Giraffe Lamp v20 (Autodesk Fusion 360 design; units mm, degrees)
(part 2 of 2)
sketch "Sketch2" plane through (0, 42, 0) normal (0, 1, 0) x axis (-1, 0, 0)
  line L1 (-90, 0) -> (-148, 0)
  line L2 (-90, 28) -> (-90, 0)
  line L3 (-148, 28) -> (-90, 28)
  line L4 (-148, 0) -> (-148, 28)
  line L5 (-125.9, 0) -> (-104.4, 0)
  line L6 (-125.9, 13) -> (-125.9, 0)
  line L7 (-104.4, 13) -> (-125.9, 13)
  line L8 (-104.4, 0) -> (-104.4, 13)
  line L9 (-93, 28) -> (-93, 3)
  line L10 (-148, 0) -> (-90, 0)
  line L11 (-148, 6.5) -> (-90, 6.5)
  line L12 (-148, 21.5) -> (-148, 6.5)
  line L13 (-90, 21.5) -> (-148, 21.5)
  line L14 (-90, 6.5) -> (-90, 21.5)
  line L15 (-103, 6.5) -> (-93, 6.5)
  line L16 (-103, 9.5) -> (-103, 6.5)
  line L17 (-93, 9.5) -> (-103, 9.5)
  line L18 (-93, 6.5) -> (-93, 9.5)
  line L19 (-145, 6.5) -> (-135, 6.5)
  line L20 (-145, 9.5) -> (-145, 6.5)
  line L21 (-135, 9.5) -> (-145, 9.5)
  line L22 (-135, 6.5) -> (-135, 9.5)
  line L23 (-103, 18.5) -> (-93, 18.5)
  line L24 (-103, 21.5) -> (-103, 18.5)
  line L25 (-93, 21.5) -> (-103, 21.5)
  line L26 (-93, 18.5) -> (-93, 21.5)
  line L27 (-145, 18.5) -> (-135, 18.5)
  line L28 (-145, 21.5) -> (-145, 18.5)
  line L29 (-135, 21.5) -> (-145, 21.5)
  line L30 (-135, 18.5) -> (-135, 21.5)
  point P6 (-104.4, 0)
  point P7 (-125.9, 0)
  point P9 (-104.4, 13)
  point P14 (-90, 6.5)
  point P17 (-90, 21.5)
  point P18 (-93, 6.5)
  point P19 (-103, 6.5)
  point P21 (-93, 9.5)
  dimension "d750" distance P6 P7 = 21.5
  dimension "d751" distance P6 P9 = 13 (= "10 mm + pcb_holder_thickness")
  dimension "d753" distance L8 L9 = 11.4
  dimension "d761" distance P14 P17 = 15 (= "Face1_to_2")
  dimension "d762" distance P18 P19 = 10
  dimension "d763" distance P18 P21 = 3 (= "pcb_holder_thickness")
  dimension "d766" R-Pattern1-uDistance = -42 (= "-pcb_X + 10 mm")
  dimension "d767" R-Pattern1-vDistance = 12 (= "Face1_to_2 - pcb_holder_thickness")
sketch "Sketch3" plane through (0, -13, 0) normal (0, -1, 0) x axis (1, 0, 0)
  line L1 (148, 0) -> (90, 0)
  line L2 (148, 28) -> (148, 0)
  line L3 (90, 28) -> (148, 28)
  line L4 (90, 0) -> (90, 28)
  line L5 (138, 28) -> (122, 28)
  line L6 (138, 25) -> (138, 28)
  line L7 (122, 25) -> (138, 25)
  line L8 (122, 28) -> (122, 25)
  line L9 (145, 28) -> (145, 3)
  point P6 (122, 28)
  point P7 (138, 28)
  point P9 (122, 25)
  dimension "d756" distance P6 P7 = 16
  dimension "d757" distance P6 P9 = 3
  dimension "d758" distance L6 L9 = 7
extrude "Extrude4" sketch "Sketch3" profile of L3 L5 L6 L7 L8 no distance stored
extrude "Extrude5" sketch "Sketch2" profile of L9 L11 L13 L15 L16 L17 L18 L19 L20 L21 L22 L23 L24 L25 L26 L27 L28 L29 L30 blind 10
fillet "Fillet1" radius 5
extrude "Extrude3" sketch "Sketch2" profile of L1 L5 L6 L7 L8 L10 no distance stored
position "Position8"
joint "Assemble25" alignAngle -30 alignOffsetX 0 alignOffsetY 0 alignOffsetZ 0
sketch "Sketch2" plane through (0, 3, 0) normal (0, 1, 0) x axis (-1, 0, 0)
  line L1 (264.3015, -79.5821) -> (253.0159, -61.0056)
  line L2 (261.7376, -81.1397) -> (264.3015, -79.5821)
  line L3 (250.2825, -62.2843) -> (261.7376, -81.1397)
  line L4 (346.5917, -63.6918) -> (423.9101, -61.7918)
  line L5 (346.518, -60.6927) -> (346.5917, -63.6918)
  line L6 (424.0216, -58.7881) -> (346.518, -60.6927)
  line L7 (404.6538, -49.3613) -> (406.365, -38.0363)
  line L8 (401.6874, -48.9131) -> (404.6538, -49.3613)
  line L9 (403.479, -37.0562) -> (401.6874, -48.9131)
  line L10 (381.5227, -41.8271) -> (391.5197, -41.5814)
  line L11 (381.7684, -51.8241) -> (381.5227, -41.8271)
  line L12 (378.7693, -51.8978) -> (381.7684, -51.8241)
  line L13 (378.5236, -41.9008) -> (378.7693, -51.8978)
  line L14 (363.5282, -42.2693) -> (378.5236, -41.9008)
  line L15 (363.7738, -52.2663) -> (363.5282, -42.2693)
  line L16 (360.7747, -52.34) -> (363.7738, -52.2663)
  line L17 (360.5291, -42.3447) -> (360.7747, -52.34)
  line L18 (352.5161, -42.5416) -> (360.5291, -42.3447)
  line L19 (338.4853, -45.7388) -> (331.2966, -32.4478)
  line L20 (335.8466, -47.166) -> (338.4853, -45.7388)
  line L21 (328.7104, -33.9723) -> (335.8466, -47.166)
  line L22 (303.2357, -50.7747) -> (328.7104, -33.9723)
  line L23 (301.5839, -48.2704) -> (303.2357, -50.7747)
  line L24 (327.5614, -31.1364) -> (301.5839, -48.2704)
  line L25 (253.0159, -61.0056) -> (293.885, -40.3968)
  line L26 (276.3126, -105.1308) -> (279.5515, -110.7585)
  line L27 (326.6272, -76.2737) -> (276.3126, -105.1308)
  line L28 (335.512, -91.6693) -> (326.6272, -76.2737)
  circle C1 centre (251.8048, -98.0857) radius 3
  circle C2 centre (297.583, -75.9965) radius 6
  arc A1 centre (237.9246, -55.6761) radius 14.0138 clockwise from (250.2825, -62.2843) to (248.2866, -65.1109)
  arc A2 centre (265.0043, -90.0088) radius 29.9898 clockwise from (265, -119.9986) to (248.2866, -65.1109)
  arc A3 centre (265.0004, -104.4994) radius 15.4992 clockwise from (278.1678, -112.6753) to (265, -119.9986)
  arc A4 centre (292.6106, -121.6427) radius 17.0002 clockwise from (278.1678, -112.6753) to (297.6595, -105.4096)
  arc A5 centre (305.9733, -78.6726) radius 27.9997 clockwise from (324.1949, -99.932) to (297.6595, -105.4096)
  arc A6 centre (382.7624, -168.2688) radius 90.0004 clockwise from (324.1949, -99.932) to (396.2531, -79.2852)
  arc A7 centre (399.9843, -54.5747) radius 24.9906 clockwise from (423.9101, -61.7918) to (396.2531, -79.2852)
  arc A8 centre (403.7415, -61.7856) radius 20.5005 clockwise from (411.4762, -42.8002) to (424.0216, -58.7881)
  arc A9 centre (401.093, -48.8166) radius 12.0003 clockwise from (406.365, -38.0363) to (411.4762, -42.8002)
  arc A10 centre (401.0931, -48.8167) radius 12 clockwise from (391.5197, -41.5814) to (403.479, -37.0562)
  arc A11 centre (352.0728, -24.5455) radius 18.0016 clockwise from (352.5161, -42.5416) to (340.0285, -37.9243)
  arc A12 centre (319.9606, -60.2216) radius 29.9982 clockwise from (331.2966, -32.4478) to (340.0285, -37.9243)
  arc A13 centre (320.0013, -60.1969) radius 30.0278 clockwise from (301.4762, -36.5645) to (327.5614, -31.1364)
  arc A14 centre (288.0365, -19.3769) radius 21.8183 clockwise from (301.4762, -36.5645) to (293.885, -40.3968)
extrude "Extrude2" cut sketch "Sketch2" profile of A4 A5 A6 L26 L27 L28 along a picked direction to an object
sketch "Sketch1" plane through (0, 0, 0) normal (0, -1, 0) x axis (1, 0, 0)
  line L1 (-253.0159, -61.0056) -> (-264.3015, -79.5821)
  line L2 (-293.8849, -40.3968) -> (-253.0159, -61.0056)
  line L3 (-301.5839, -48.2704) -> (-327.5614, -31.1364)
  line L4 (-303.2357, -50.7747) -> (-301.5839, -48.2704)
  line L5 (-328.7104, -33.9723) -> (-303.2357, -50.7747)
  line L6 (-335.8466, -47.166) -> (-328.7104, -33.9723)
  line L7 (-338.4853, -45.7388) -> (-335.8466, -47.166)
  line L8 (-331.2966, -32.4478) -> (-338.4853, -45.7388)
  line L9 (-360.5291, -42.3447) -> (-352.516, -42.5416)
  line L10 (-360.7747, -52.34) -> (-360.5291, -42.3447)
  line L11 (-363.7738, -52.2663) -> (-360.7747, -52.34)
  line L12 (-363.5282, -42.2693) -> (-363.7738, -52.2663)
  line L13 (-378.5236, -41.9008) -> (-363.5282, -42.2693)
  line L14 (-378.7693, -51.8978) -> (-378.5236, -41.9008)
  line L15 (-381.7684, -51.8241) -> (-378.7693, -51.8978)
  line L16 (-381.5227, -41.8271) -> (-381.7684, -51.8241)
  line L17 (-391.5196, -41.5814) -> (-381.5227, -41.8271)
  line L18 (-401.6874, -48.9131) -> (-403.479, -37.0562)
  line L19 (-404.6538, -49.3613) -> (-401.6874, -48.9131)
  line L20 (-406.3649, -38.0363) -> (-404.6538, -49.3613)
  line L21 (-346.518, -60.6927) -> (-424.0216, -58.7882)
  line L22 (-346.5917, -63.6918) -> (-346.518, -60.6927)
  line L23 (-423.91, -61.7918) -> (-346.5917, -63.6918)
  line L24 (-261.7375, -81.1397) -> (-250.2825, -62.2843)
  line L25 (-264.3015, -79.5821) -> (-261.7375, -81.1397)
  line L26 (-326.6271, -76.2737) -> (-335.512, -91.6693)
  line L27 (-276.3126, -105.1309) -> (-326.6271, -76.2737)
  line L28 (-279.5515, -110.7585) -> (-276.3126, -105.1309)
  circle C1 centre (-251.8048, -98.0857) radius 3
  circle C2 centre (-297.583, -75.9965) radius 6
  arc A1 centre (-288.0365, -19.3769) radius 21.8183 clockwise from (-293.8849, -40.3968) to (-301.4762, -36.5645)
  arc A2 centre (-320.0013, -60.1969) radius 30.0278 clockwise from (-327.5614, -31.1364) to (-301.4762, -36.5645)
  arc A3 centre (-319.9606, -60.2216) radius 29.9982 clockwise from (-340.0285, -37.9243) to (-331.2966, -32.4478)
  arc A4 centre (-352.0727, -24.5455) radius 18.0016 clockwise from (-340.0285, -37.9243) to (-352.516, -42.5416)
  arc A5 centre (-401.0931, -48.8167) radius 12 clockwise from (-403.479, -37.0562) to (-391.5196, -41.5814)
  arc A6 centre (-401.093, -48.8166) radius 12.0003 clockwise from (-411.4762, -42.8002) to (-406.3649, -38.0363)
  arc A7 centre (-403.7415, -61.7856) radius 20.5005 clockwise from (-424.0216, -58.7882) to (-411.4762, -42.8002)
  arc A8 centre (-399.9843, -54.5747) radius 24.9906 clockwise from (-396.2531, -79.2852) to (-423.91, -61.7918)
  arc A9 centre (-382.7624, -168.2688) radius 90.0004 clockwise from (-396.2531, -79.2852) to (-335.512, -91.6693)
  arc A10 centre (-292.6105, -121.6427) radius 17.0002 clockwise from (-279.5515, -110.7585) to (-278.1678, -112.6753)
  arc A11 centre (-265.0004, -104.4994) radius 15.4992 clockwise from (-265, -119.9986) to (-278.1678, -112.6753)
  arc A12 centre (-265.0042, -90.0088) radius 29.9898 clockwise from (-248.2865, -65.1109) to (-265, -119.9986)
  arc A13 centre (-237.9246, -55.6761) radius 14.0138 clockwise from (-248.2865, -65.1109) to (-250.2825, -62.2843)
extrude "Extrude1" new body sketch "Thug Life glasses" profile of L1 L2 L3 L4 L5 L6 L7 L8 L9 L10 L11 L19 L12 L13 L14 L15 L16 L17 along normal blind 3 (= "Thickness")
sketch "Sketch4" plane through (0, 3, 0) normal (0, 1, 0) x axis (-1, 0, 0)
  line L1 (179.3475, -84.0435) -> (190, -82.8095)
  line L2 (177.7875, -81.2041) -> (178.0387, -83.3727)
  line L3 (177.209, -81.2711) -> (177.7875, -81.2041)
  curve K1 (177.209, -81.2711) -> (157.551, -61.7546)
  line L4 (156.5, -61.7546) -> (157.551, -61.7546)
  curve K2 (156.5, -61.7546) -> (144.8507, -76.5991)
  line L5 (138, -96.1735) -> (144.8507, -76.5991)
  line L6 (138, -120) -> (138, -96.1735)
  line L7 (190, -101.0735) -> (138, -120)
  line L8 (190, -99.1735) -> (190, -101.0735)
  line L9 (159.5, -99.1735) -> (190, -99.1735)
  line L10 (159.5, -96.1735) -> (159.5, -99.1735)
  line L11 (190, -96.1735) -> (159.5, -96.1735)
  line L12 (190, -82.8095) -> (190, -96.1735)
  arc A1 centre (193.315, -55.1792) radius 32.0662 clockwise from (179.3475, -84.0435) to (178.0387, -83.3727)
sketch "Sketch3" plane through (0, 3, 0) normal (0, 1, 0) x axis (-1, 0, 0)
  line L1 (394, -22.5177) -> (371, -22.5177)
  line L2 (414.3235, 142.703) -> (429.2349, 121.5322)
  line L3 (394, 142.703) -> (414.3235, 142.703)
  line L4 (394, 55.5559) -> (394, 142.703)
  line L5 (391, 55.5559) -> (394, 55.5559)
  line L6 (391, 142.703) -> (391, 55.5559)
  line L7 (376, 142.703) -> (391, 142.703)
  line L8 (376, 55.5559) -> (376, 142.703)
  line L9 (373, 55.5559) -> (376, 55.5559)
  line L10 (373, 142.703) -> (373, 55.5559)
  line L11 (352.6765, 142.703) -> (373, 142.703)
  line L12 (336.5, 122.4823) -> (352.6765, 142.703)
  circle C1 centre (356.5, 120.1478) radius 6
  circle C2 centre (411.5, 120.1478) radius 6
  arc A1 centre (306.9189, 35.4376) radius 50 clockwise from (340.5, 72.4823) to (352.9482, 15.9105)
  arc A2 centre (382.5, 3.3737) radius 32.1011 clockwise from (350.9441, -2.5177) to (352.9482, 15.9105)
  arc A3 centre (375.5195, 2.0704) radius 25 clockwise from (371, -22.5177) to (350.9441, -2.5177)
  arc A4 centre (389.4805, 2.0704) radius 25 clockwise from (414.0559, -2.5177) to (394, -22.5177)
  arc A5 centre (382.5, 3.3737) radius 32.1011 clockwise from (412.0518, 15.9105) to (414.0559, -2.5177)
  arc A6 centre (458.0811, 35.4376) radius 50 clockwise from (412.0518, 15.9105) to (424.5, 72.4823)
  arc A7 centre (399.9091, 99.6096) radius 36.6142 clockwise from (429.2349, 121.5322) to (424.5, 72.4823)
  arc A8 centre (365.0909, 99.6096) radius 36.6142 clockwise from (340.5, 72.4823) to (336.5, 122.4823)
copy_paste "CutPaste1"
copy_paste "CutPaste14"
joint "Assemble5" alignAngle -90 alignOffsetX 0 alignOffsetY 0 alignOffsetZ 0
joint "Assemble6" alignAngle -90 alignOffsetX 0 alignOffsetY 0 alignOffsetZ 0
sketch "Sketch2" plane through (0, 3, 0) normal (0, 1, 0) x axis (-1, 0, 0)
  line L1 (88.2284, 185.2799) -> (234.6284, 185.2799)
  line L2 (88.2284, 175.8604) -> (88.2284, 185.2799)
  line L3 (95.7284, 175.8604) -> (88.2284, 175.8604)
  line L4 (95.7284, 168.3604) -> (95.7284, 175.8604)
  line L5 (103.2284, 168.3604) -> (95.7284, 168.3604)
  line L6 (103.2284, 160.8604) -> (103.2284, 168.3604)
  line L7 (110.7284, 160.8604) -> (103.2284, 160.8604)
  line L8 (110.7284, 153.3604) -> (110.7284, 160.8604)
  line L9 (135.9284, 153.3604) -> (110.7284, 153.3604)
  line L10 (135.9284, 160.8604) -> (135.9284, 153.3604)
  line L11 (143.4284, 160.8604) -> (135.9284, 160.8604)
  line L12 (143.4284, 168.3604) -> (143.4284, 160.8604)
  line L13 (150.9284, 168.3604) -> (143.4284, 168.3604)
  line L14 (150.9284, 170.2799) -> (150.9284, 168.3604)
  line L15 (153.9284, 170.2799) -> (150.9284, 170.2799)
  line L16 (153.9284, 177.7799) -> (153.9284, 170.2799)
  line L17 (168.9284, 177.7799) -> (153.9284, 177.7799)
  line L18 (168.9284, 170.2799) -> (168.9284, 177.7799)
  line L19 (171.9284, 170.2799) -> (168.9284, 170.2799)
  line L20 (171.9284, 168.3604) -> (171.9284, 170.2799)
  line L21 (179.4284, 168.3604) -> (171.9284, 168.3604)
  line L22 (179.4284, 160.8604) -> (179.4284, 168.3604)
  line L23 (186.9284, 160.8604) -> (179.4284, 160.8604)
  line L24 (186.9284, 153.3604) -> (186.9284, 160.8604)
  line L25 (212.1284, 153.3604) -> (186.9284, 153.3604)
  line L26 (212.1284, 160.8604) -> (212.1284, 153.3604)
  line L27 (219.6284, 160.8604) -> (212.1284, 160.8604)
  line L28 (219.6284, 168.3604) -> (219.6284, 160.8604)
  line L29 (227.1284, 168.3604) -> (219.6284, 168.3604)
  line L30 (227.1284, 175.8604) -> (227.1284, 168.3604)
  line L31 (234.6284, 175.8604) -> (227.1284, 175.8604)
  line L32 (234.6284, 185.2799) -> (234.6284, 175.8604)
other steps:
split "Split1"
extrude "Extrude2" cut sketch "Sketch2" profile of A4 A5 A6 L26 L27 L28 along a picked direction to an object
create_component "CreateComponent2"
create_component "CreateComponent4"
create_component "CreateComponent5"
create_component "CreateComponent6"
create_component "CreateComponent7"
create_component "CreateComponent8"
create_component "CreateComponent9"
create_component "CreateComponent10"
create_component "CreateComponent11"
create_component "CreateComponent12"
create_component "CreateComponent14"
create_component "CreateComponent15"
create_component "CreateComponent18"
joint_origin "JointOrigin1" OffsetX 0 OffsetY 0 OffsetZ 0 AngleZ 0
joint_origin "JointOrigin1" OffsetX 0 OffsetY 0 OffsetZ 0 AngleZ 0
joint_origin "JointOrigin2" OffsetX 0 OffsetY 0 OffsetZ 0 AngleZ 0
joint_origin "JointOrigin2" OffsetX 0 OffsetY 0 OffsetZ 0 AngleZ 0
joint_origin "JointOrigin1" OffsetX 0 OffsetY 0 OffsetZ 0 AngleZ 0
joint_origin "JointOrigin2" OffsetX 0 OffsetY 0 OffsetZ 0 AngleZ 0
joint_origin "JointOrigin1" OffsetX 0 OffsetY 0 OffsetZ 0 AngleZ 0
joint_origin "JointOrigin3" OffsetX 0 OffsetY 0 OffsetZ 0 AngleZ 0
joint_origin "JointOrigin2" OffsetX 0 OffsetY 0 OffsetZ 0 AngleZ 0
joint_origin "JointOrigin4" OffsetX 0 OffsetY 0 OffsetZ 0 AngleZ 0
joint_origin "JointOrigin7" OffsetX 0 OffsetY 0 OffsetZ 0 AngleZ 0
joint_origin "JointOrigin28" OffsetX 0 OffsetY 0 OffsetZ 0 AngleZ 0
joint_origin "JointOrigin29" OffsetX 0 OffsetY 0 OffsetZ 0 AngleZ 0
joint_origin "JointOrigin8" OffsetX 0 OffsetY 0 OffsetZ 0 AngleZ 0
joint_origin "JointOrigin5" OffsetX 0 OffsetY 0 OffsetZ 0 AngleZ 0
joint_origin "JointOrigin32" OffsetX 0 OffsetY 0 OffsetZ 0 AngleZ 0
joint_origin "JointOrigin3" OffsetX 0 OffsetY 0 OffsetZ 0 AngleZ 0
joint_origin "JointOrigin33" OffsetX 0 OffsetY 0 OffsetZ 0 AngleZ 0
joint_origin "JointOrigin6" OffsetX 0 OffsetY 0 OffsetZ 0 AngleZ 0
joint_origin "JointOrigin34" OffsetX 0 OffsetY 0 OffsetZ 0 AngleZ 0
joint_origin "JointOrigin4" OffsetX 0 OffsetY 0 OffsetZ 0 AngleZ 0
joint_origin "JointOrigin35" OffsetX 0 OffsetY 0 OffsetZ 0 AngleZ 0
joint_origin "JointOrigin17" OffsetX 0 OffsetY 0 OffsetZ 0 AngleZ 0
joint_origin "JointOrigin50" OffsetX 0 OffsetY 0 OffsetZ 0 AngleZ 0
create_component "CreateComponent20"
remove_instance "RemoveInstance14"
remove_instance "RemoveInstance15"
remove_instance "RemoveInstance16"
remove_instance "RemoveInstance17"
remove_instance "RemoveInstance18"
remove_instance "RemoveInstance19"
remove_instance "RemoveInstance20"
remove_instance "RemoveInstance22"
remove_instance "RemoveInstance23"
remove_instance "RemoveInstance24"
remove_instance "RemoveInstance25"
remove_instance "RemoveInstance26"
joint_origin "JointOrigin10" sketch "Sketch2" OffsetX 0 OffsetY 0 OffsetZ 0 AngleZ 0
joint_origin "JointOrigin53" OffsetX 0 OffsetY 0 OffsetZ 0 AngleZ 0
joint_origin "JointOrigin11" sketch "Sketch2" OffsetX 0 OffsetY 0 OffsetZ 0 AngleZ 0
joint_origin "JointOrigin54" OffsetX 0 OffsetY 0 OffsetZ 0 AngleZ 0
joint_origin "JointOrigin1" OffsetX 0 OffsetY 0 OffsetZ 0 AngleZ 0
joint_origin "JointOrigin2" OffsetX 0 OffsetY 0 OffsetZ 0 AngleZ 0
create_component "CreateComponent21"
joint_origin "JointOrigin5" OffsetX 0 OffsetY 0 OffsetZ 0 AngleZ 0
joint_origin "JointOrigin56" OffsetX 0 OffsetY 0 OffsetZ 0 AngleZ 0
extrude "Extrude6" cut sketch "Sketch2" profile of A4 A5 A6 L26 L27 L28 along a picked direction to an object
create_component "CreateComponent22"
remove_instance "RemoveInstance27"
remove_instance "RemoveInstance1"
joint_origin "JointOrigin1" OffsetX 0 OffsetY 0 OffsetZ 0 AngleZ 0
joint_origin "JointOrigin57" OffsetX 0 OffsetY 0 OffsetZ 0 AngleZ 0
joint_origin "JointOrigin2" OffsetX 0 OffsetY 0 OffsetZ 0 AngleZ 0
joint_origin "JointOrigin58" OffsetX 0 OffsetY 0 OffsetZ 0 AngleZ 0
